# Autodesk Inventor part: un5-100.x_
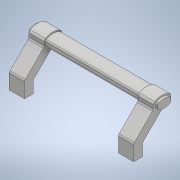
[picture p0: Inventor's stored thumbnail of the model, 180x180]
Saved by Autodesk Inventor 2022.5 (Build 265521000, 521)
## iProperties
Part Number: un5-100.x_
Material: 一般
Document SubType Name: Modeling
Designer: ImaoCorp
Density: 1 g/cm^3
Appearance: 既定
Sending System: SOLIDWORKS 2017-2017317
MC: AMD64
MC_MODEL: Intel64 Family 6 Model 60 Stepping 3, GenuineIntel
OS: Windows_NT
FRU: Parasolid Version 29.0, build 201,  4-17-2017
FORMAT: text
GUISE: transmit
KEY: un5-100
FILE: un5-100.x_t
DATE: Thu Sep 19 11:10:14 2019
Author: ImaoCorp
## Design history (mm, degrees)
feature "Base1"
node "ソリッド1"
